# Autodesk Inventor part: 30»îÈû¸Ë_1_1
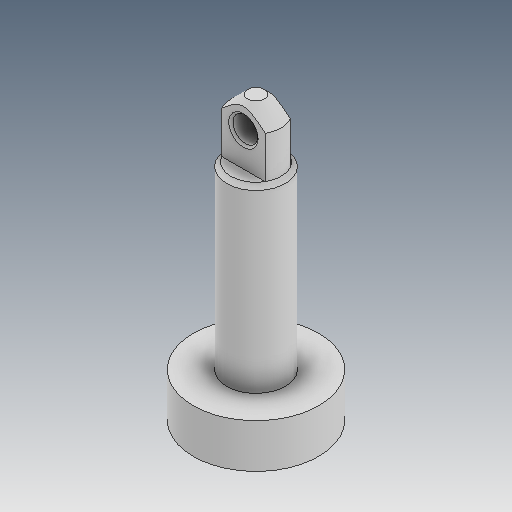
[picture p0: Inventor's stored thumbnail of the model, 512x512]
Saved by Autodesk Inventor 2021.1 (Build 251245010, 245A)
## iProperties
Created: 2019-04
Part Number: 30»îÈû¸Ë_1_1
Material: Ogólny
Document SubType Name: Modeling
Designer: user
Density: 1 g/cm^3
Appearance: Domyślna
Author: user
Revision Number: ÈÎºÎ
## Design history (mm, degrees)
feature "Í¹Ì¨-À­Éì2"
node "Bryła1"
